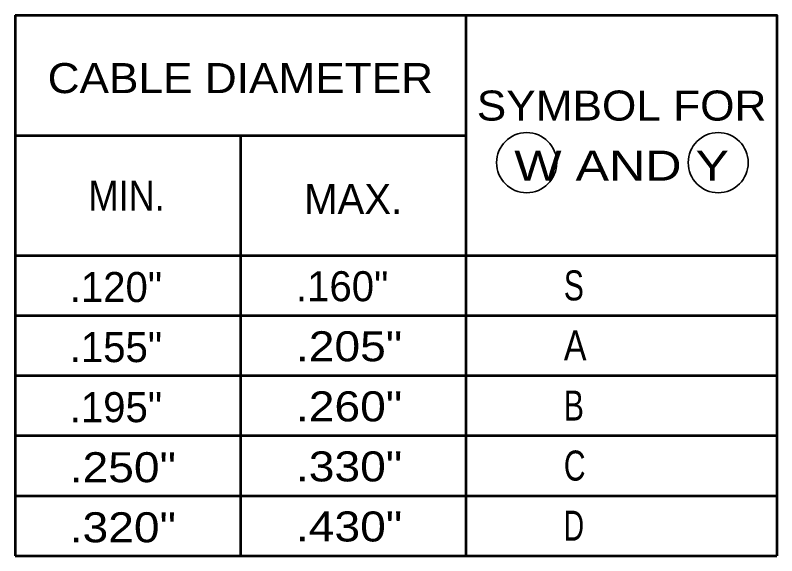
# Model space of a CAD drawing. Extents: x -1 to 679, y 0 to 440.
# Drawn here: x 291.3 to 342, y 72.7 to 108.7 of the extents above; entities that cross this region are included whole.
import ezdxf
from ezdxf.enums import TextEntityAlignment as Align

# ---------------------------------------------------------------- set-up
doc = ezdxf.new("R2010")
doc.units = 0
doc.header["$LTSCALE"] = 0.8
doc.layers.add('1', color=7, linetype='Continuous', lineweight=53)

msp = doc.modelspace()

# ---------------------------------------------------------------- linework, layer by layer
at = {"layer": '1'}
for p, q in [((291.2524, 108.6769), (291.2524, 72.6769)), ((321.2524, 108.6769), (321.2524, 72.6769)), ((291.2524, 100.6769), (321.2524, 100.6769)), ((306.2524, 100.6769), (306.2524, 72.6769)), ((291.2524, 92.6769), (341.9642, 92.6769)), ((291.2524, 88.6769), (341.9642, 88.6769)), ((291.2524, 84.6769), (341.9642, 84.6769)), ((291.2524, 80.6769), (341.9642, 80.6769)), ((291.2524, 76.6769), (341.9642, 76.6769)), ((291.2524, 72.6769), (341.9642, 72.6769))]:
    msp.add_line(p, q, dxfattribs=at)
msp.add_lwpolyline([(291.2524, 108.6769), (341.9642, 108.6769), (341.9642, 72.6769)], dxfattribs=at)
at = {"layer": '1', "lineweight": 35}
for centre in [(325.3087, 98.8578), (338.0655, 98.8578)]:
    msp.add_circle(centre, 2, dxfattribs=at)

# ---------------------------------------------------------------- texts
at = {"layer": '1'}
for s, width, p in [('CABLE DIAMETER', 1.1, (293.4101, 103.489)), ('MIN.', 0.9, (296.1295, 95.6547)), ('S', 0.75, (327.7829, 89.6831)), ('.205"', 1.15, (309.9438, 85.6287)), ('A', 0.85, (327.7829, 85.6831)), ('B', 0.75, (327.7829, 81.6831)), ('.260"', 1.15, (309.9438, 81.6287)), ('.330"', 1.15, (309.9438, 77.6287)), ('C', 0.75, (327.7829, 77.6831)), ('.250"', 1.15, (294.8786, 77.5742)), ('.320"', 1.15, (294.8786, 73.5742)), ('.430"', 1.15, (309.9438, 73.6287)), ('D', 0.7, (327.7829, 73.6831))]:
    msp.add_text(s, height=2, dxfattribs=dict(at, width=width)).set_placement(p)
for s, width, p in [('SYMBOL FOR', 1.1, (331.6312, 101.6599)), ('W AND Y', 1.25, (331.6312, 97.6599))]:
    msp.add_text(s, height=2, dxfattribs=dict(at, width=width)).set_placement(p, align=Align.CENTER)
for s, p in [('MAX.', (310.4878, 95.437)), ('.120"', (294.8786, 89.5742)), ('.160"', (309.9438, 89.6287)), ('.155"', (294.8786, 85.5742)), ('.195"', (294.8786, 81.5742))]:
    msp.add_text(s, height=2, dxfattribs=at).set_placement(p)

doc.saveas('drawing.dxf')
